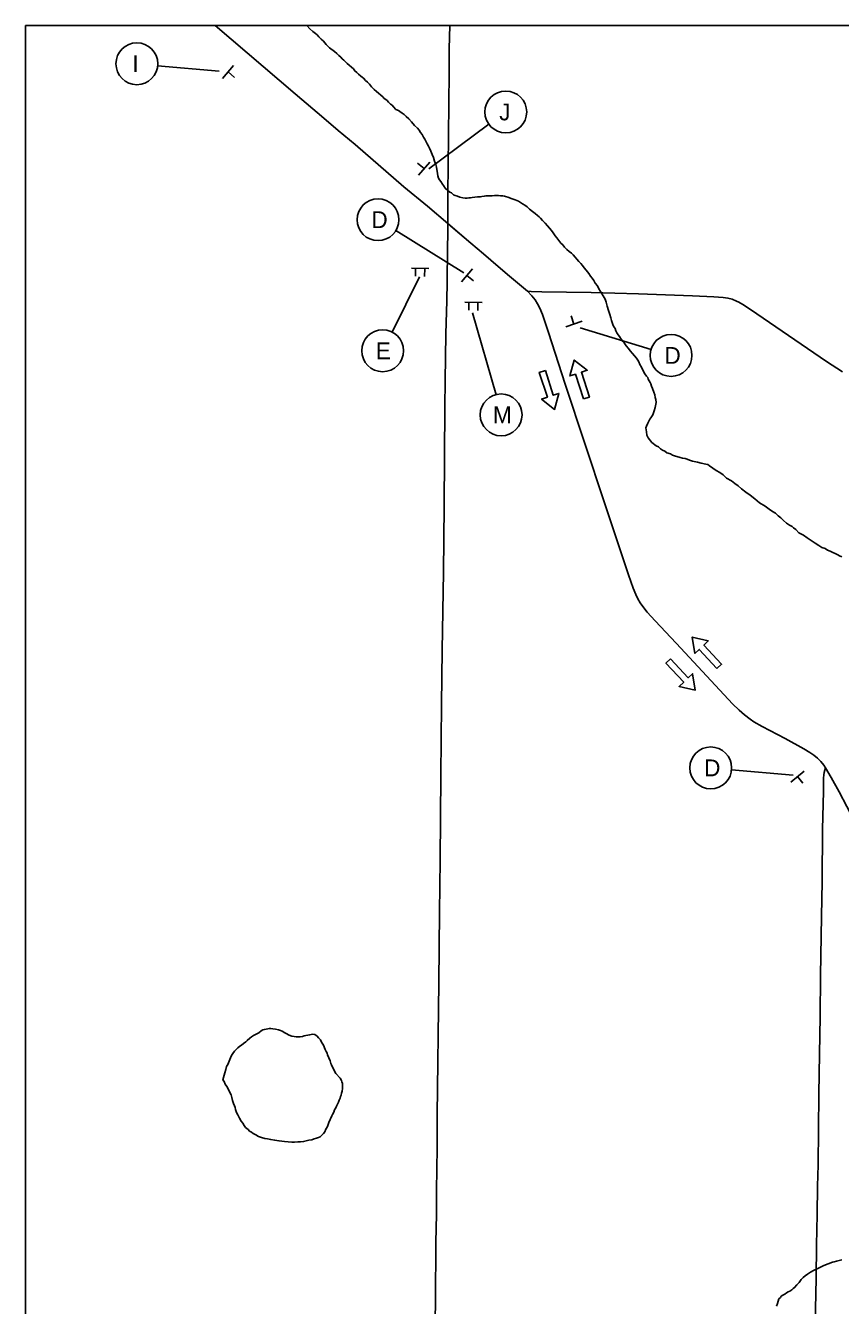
# Model space of a CAD drawing. Extents: x 1633.3 to 1707.6, y 1081.5 to 1106.
# Drawn here: x 1633.31 to 1640.87, y 1094.16 to 1106.02 of the extents above; entities that cross this region are included whole.
import ezdxf

# ---------------------------------------------------------------- set-up
doc = ezdxf.new("R2010")
doc.units = 0
for name, color, linetype in [('GM_X_County_Road', 7, 'Continuous'), ('GM_X_Minor_Lake', 7, 'Continuous'), ('GM_X_Minor_River', 7, 'Continuous'), ('GM_X_State_Route', 7, 'Continuous'), ('GM_X_Township_Road', 7, 'Continuous'), ('SH_Data', 7, 'Continuous'), ('SH_Text', 7, 'Continuous'), ('SN_P_Signs', 7, 'Continuous')]:
    doc.layers.add(name, color=color, linetype=linetype)

msp = doc.modelspace()

# ---------------------------------------------------------------- linework, layer by layer
at = {"layer": 'GM_X_County_Road'}
for points in [[(1637.23, 1104.185), (1637.23, 1104.472), (1637.232, 1104.713), (1637.241, 1105.587), (1637.241, 1105.806), (1637.246, 1106.021)], [(1637.108, 1093.581), (1637.115, 1094.281), (1637.118, 1094.653), (1637.118, 1094.74), (1637.123, 1095.003), (1637.123, 1095.221), (1637.128, 1095.615), (1637.131, 1095.922), (1637.145, 1097.147), (1637.148, 1097.476), (1637.152, 1097.802), (1637.157, 1098.283), (1637.163, 1099.071), (1637.171, 1099.728), (1637.177, 1100.231), (1637.189, 1100.953), (1637.195, 1101.566), (1637.201, 1102.485), (1637.203, 1102.726), (1637.21, 1103.164), (1637.218, 1103.47), (1637.221, 1103.645), (1637.225, 1103.952), (1637.228, 1104.104), (1637.23, 1104.185)]]:
    msp.add_lwpolyline(points, dxfattribs=at)
at = {"layer": 'GM_X_Minor_Lake'}
for points in [[(1636.191, 1096.306), (1636.16, 1096.364), (1636.15, 1096.386), (1636.144, 1096.399), (1636.137, 1096.424), (1636.113, 1096.48), (1636.108, 1096.494), (1636.1, 1096.51), (1636.092, 1096.529), (1636.084, 1096.545), (1636.077, 1096.561), (1636.069, 1096.577), (1636.058, 1096.596), (1636.048, 1096.618), (1636.029, 1096.637), (1636.016, 1096.653), (1635.995, 1096.667), (1635.976, 1096.669), (1635.96, 1096.667), (1635.946, 1096.664), (1635.93, 1096.662), (1635.911, 1096.657), (1635.895, 1096.654), (1635.879, 1096.649), (1635.857, 1096.644), (1635.836, 1096.644), (1635.822, 1096.645), (1635.804, 1096.648), (1635.782, 1096.653), (1635.756, 1096.662), (1635.729, 1096.675), (1635.716, 1096.684), (1635.692, 1096.697), (1635.675, 1096.703), (1635.657, 1096.711), (1635.63, 1096.717), (1635.606, 1096.72), (1635.587, 1096.723), (1635.574, 1096.723), (1635.528, 1096.715), (1635.514, 1096.71), (1635.498, 1096.7), (1635.474, 1096.684), (1635.452, 1096.671), (1635.439, 1096.663), (1635.425, 1096.658), (1635.409, 1096.647), (1635.393, 1096.632), (1635.368, 1096.61), (1635.355, 1096.6), (1635.333, 1096.584), (1635.314, 1096.568), (1635.3, 1096.558), (1635.281, 1096.542), (1635.262, 1096.526), (1635.251, 1096.513), (1635.235, 1096.492), (1635.221, 1096.473), (1635.213, 1096.452), (1635.205, 1096.436), (1635.199, 1096.42), (1635.188, 1096.39), (1635.177, 1096.369), (1635.169, 1096.343), (1635.161, 1096.311)], [(1635.161, 1096.311), (1635.143, 1096.248), (1635.154, 1096.23), (1635.164, 1096.206), (1635.178, 1096.184), (1635.218, 1096.109), (1635.226, 1096.082), (1635.231, 1096.056), (1635.242, 1096.029), (1635.25, 1096.005), (1635.255, 1095.991), (1635.26, 1095.973), (1635.268, 1095.943), (1635.281, 1095.922), (1635.297, 1095.892), (1635.313, 1095.865), (1635.327, 1095.844), (1635.34, 1095.822), (1635.353, 1095.806), (1635.375, 1095.785), (1635.388, 1095.771), (1635.407, 1095.761), (1635.423, 1095.75), (1635.447, 1095.736), (1635.471, 1095.723), (1635.5, 1095.712), (1635.53, 1095.704), (1635.557, 1095.699), (1635.586, 1095.693), (1635.621, 1095.688), (1635.664, 1095.68), (1635.712, 1095.674), (1635.749, 1095.671), (1635.781, 1095.669), (1635.805, 1095.668), (1635.837, 1095.671), (1635.862, 1095.671), (1635.891, 1095.674), (1635.915, 1095.681), (1635.939, 1095.687), (1635.966, 1095.692), (1635.99, 1095.7), (1636.011, 1095.705), (1636.028, 1095.711), (1636.044, 1095.719), (1636.057, 1095.732), (1636.076, 1095.748), (1636.087, 1095.764), (1636.097, 1095.788), (1636.108, 1095.807), (1636.116, 1095.825), (1636.124, 1095.852), (1636.154, 1095.913), (1636.159, 1095.927), (1636.17, 1095.946), (1636.178, 1095.97), (1636.189, 1095.986), (1636.197, 1096.004), (1636.205, 1096.02), (1636.213, 1096.039), (1636.221, 1096.058), (1636.229, 1096.076), (1636.234, 1096.092), (1636.24, 1096.106), (1636.243, 1096.122), (1636.248, 1096.143), (1636.251, 1096.165), (1636.251, 1096.186), (1636.253, 1096.199), (1636.251, 1096.213), (1636.245, 1096.229), (1636.243, 1096.242), (1636.229, 1096.261), (1636.191, 1096.306)]]:
    msp.add_lwpolyline(points, dxfattribs=at)
at = {"layer": 'GM_X_Minor_River'}
for points in [[(1635.92, 1106.021), (1635.948, 1105.992), (1635.977, 1105.967), (1636.001, 1105.948), (1636.017, 1105.934), (1636.033, 1105.915), (1636.054, 1105.896), (1636.076, 1105.875), (1636.099, 1105.845)], [(1636.099, 1105.845), (1636.131, 1105.815), (1636.176, 1105.78), (1636.198, 1105.761), (1636.216, 1105.744), (1636.235, 1105.728), (1636.248, 1105.714), (1636.264, 1105.701), (1636.28, 1105.685), (1636.296, 1105.668), (1636.352, 1105.619), (1636.365, 1105.6), (1636.384, 1105.587), (1636.399, 1105.57), (1636.423, 1105.551), (1636.447, 1105.532), (1636.466, 1105.513), (1636.484, 1105.497), (1636.503, 1105.478), (1636.521, 1105.454), (1636.545, 1105.429), (1636.567, 1105.41), (1636.585, 1105.394), (1636.606, 1105.375), (1636.625, 1105.359), (1636.638, 1105.345), (1636.652, 1105.337), (1636.665, 1105.326), (1636.678, 1105.31), (1636.697, 1105.291), (1636.713, 1105.282), (1636.726, 1105.269), (1636.747, 1105.244), (1636.771, 1105.233), (1636.784, 1105.225), (1636.806, 1105.209), (1636.824, 1105.195), (1636.843, 1105.179), (1636.867, 1105.157), (1636.891, 1105.127), (1636.92, 1105.095), (1636.946, 1105.07), (1636.962, 1105.051), (1636.975, 1105.03), (1636.989, 1105.011), (1637.002, 1104.987), (1637.015, 1104.968), (1637.023, 1104.949), (1637.036, 1104.925), (1637.049, 1104.903), (1637.057, 1104.884), (1637.07, 1104.857), (1637.083, 1104.825), (1637.096, 1104.798), (1637.106, 1104.763), (1637.117, 1104.733), (1637.122, 1104.707), (1637.132, 1104.65), (1637.137, 1104.629), (1637.142, 1104.607), (1637.152, 1104.591), (1637.163, 1104.575), (1637.179, 1104.55), (1637.189, 1104.537), (1637.203, 1104.515), (1637.229, 1104.491), (1637.248, 1104.477), (1637.261, 1104.469), (1637.282, 1104.453), (1637.298, 1104.447), (1637.317, 1104.439), (1637.341, 1104.43), (1637.368, 1104.425), (1637.389, 1104.422), (1637.408, 1104.422), (1637.422, 1104.424), (1637.438, 1104.424), (1637.454, 1104.426), (1637.478, 1104.429), (1637.505, 1104.434), (1637.529, 1104.433), (1637.543, 1104.436), (1637.567, 1104.438), (1637.58, 1104.441), (1637.602, 1104.443), (1637.623, 1104.443), (1637.639, 1104.443), (1637.661, 1104.445), (1637.682, 1104.445), (1637.698, 1104.444), (1637.717, 1104.442), (1637.739, 1104.441), (1637.755, 1104.438), (1637.795, 1104.427), (1637.816, 1104.419), (1637.835, 1104.413), (1637.854, 1104.405), (1637.87, 1104.399), (1637.883, 1104.394), (1637.904, 1104.38), (1637.92, 1104.369)], [(1637.92, 1104.369), (1637.942, 1104.356), (1637.963, 1104.339), (1637.987, 1104.32), (1638.014, 1104.296), (1638.04, 1104.279), (1638.059, 1104.26), (1638.075, 1104.249), (1638.088, 1104.236), (1638.106, 1104.214), (1638.13, 1104.19), (1638.152, 1104.165), (1638.17, 1104.144), (1638.189, 1104.122), (1638.207, 1104.098), (1638.223, 1104.073), (1638.239, 1104.052), (1638.257, 1104.027), (1638.278, 1104.003), (1638.294, 1103.987), (1638.31, 1103.968), (1638.331, 1103.946), (1638.355, 1103.927), (1638.377, 1103.911), (1638.392, 1103.894), (1638.408, 1103.875), (1638.424, 1103.856), (1638.445, 1103.835), (1638.461, 1103.816), (1638.477, 1103.797), (1638.493, 1103.775), (1638.512, 1103.753), (1638.525, 1103.737), (1638.535, 1103.721), (1638.551, 1103.699), (1638.567, 1103.678), (1638.583, 1103.656), (1638.596, 1103.634), (1638.617, 1103.607), (1638.63, 1103.58), (1638.646, 1103.556), (1638.678, 1103.499), (1638.688, 1103.483), (1638.696, 1103.456), (1638.706, 1103.421), (1638.719, 1103.378), (1638.732, 1103.341), (1638.74, 1103.311), (1638.747, 1103.287), (1638.755, 1103.26), (1638.763, 1103.241), (1638.771, 1103.225), (1638.779, 1103.212), (1638.786, 1103.19), (1638.797, 1103.171), (1638.807, 1103.155), (1638.821, 1103.139), (1638.831, 1103.122), (1638.839, 1103.109), (1638.852, 1103.093), (1638.863, 1103.079), (1638.884, 1103.052), (1638.903, 1103.028), (1638.921, 1103.006), (1638.942, 1102.982), (1638.961, 1102.96), (1638.977, 1102.938), (1638.99, 1102.919), (1639, 1102.903), (1639.008, 1102.879), (1639.024, 1102.855), (1639.037, 1102.825), (1639.055, 1102.793), (1639.071, 1102.771), (1639.082, 1102.758), (1639.087, 1102.744), (1639.095, 1102.728), (1639.105, 1102.712), (1639.111, 1102.698), (1639.118, 1102.679), (1639.126, 1102.655), (1639.139, 1102.623), (1639.147, 1102.596), (1639.152, 1102.572), (1639.157, 1102.553), (1639.162, 1102.526), (1639.153, 1102.481), (1639.142, 1102.449), (1639.131, 1102.411), (1639.112, 1102.385), (1639.101, 1102.372), (1639.085, 1102.334), (1639.071, 1102.308), (1639.065, 1102.292), (1639.07, 1102.254), (1639.075, 1102.225), (1639.088, 1102.198), (1639.12, 1102.157), (1639.16, 1102.124), (1639.181, 1102.116), (1639.202, 1102.097)], [(1639.202, 1102.097), (1639.218, 1102.086), (1639.24, 1102.075), (1639.261, 1102.059), (1639.293, 1102.05), (1639.312, 1102.039), (1639.33, 1102.031), (1639.384, 1102.017), (1639.405, 1102.011), (1639.429, 1102.006), (1639.448, 1102), (1639.47, 1101.992), (1639.499, 1101.983), (1639.545, 1101.972), (1639.579, 1101.963), (1639.62, 1101.955), (1639.641, 1101.952), (1639.657, 1101.938), (1639.686, 1101.919), (1639.718, 1101.897), (1639.75, 1101.878), (1639.782, 1101.856), (1639.814, 1101.826), (1639.859, 1101.799), (1639.891, 1101.777), (1639.92, 1101.753), (1639.952, 1101.726), (1639.992, 1101.696), (1640.032, 1101.666), (1640.075, 1101.633), (1640.12, 1101.597), (1640.171, 1101.565), (1640.21, 1101.537), (1640.24, 1101.516), (1640.269, 1101.499), (1640.293, 1101.475), (1640.317, 1101.456), (1640.341, 1101.431), (1640.37, 1101.409), (1640.399, 1101.39), (1640.421, 1101.377), (1640.434, 1101.366), (1640.455, 1101.349), (1640.484, 1101.319), (1640.527, 1101.297), (1640.562, 1101.273), (1640.599, 1101.246), (1640.636, 1101.221), (1640.671, 1101.202), (1640.697, 1101.183), (1640.727, 1101.172), (1640.751, 1101.158), (1640.775, 1101.147), (1640.847, 1101.114), (1640.86, 1101.106), (1640.884, 1101.095)], [(1640.884, 1094.579), (1640.857, 1094.571), (1640.833, 1094.566), (1640.812, 1094.561), (1640.796, 1094.556), (1640.715, 1094.526), (1640.686, 1094.51), (1640.654, 1094.495), (1640.619, 1094.479), (1640.592, 1094.463), (1640.565, 1094.444), (1640.544, 1094.431), (1640.525, 1094.415), (1640.506, 1094.396), (1640.488, 1094.369), (1640.466, 1094.345), (1640.445, 1094.321), (1640.431, 1094.311), (1640.418, 1094.3), (1640.402, 1094.289), (1640.386, 1094.281), (1640.37, 1094.273), (1640.354, 1094.26), (1640.335, 1094.252), (1640.321, 1094.241), (1640.313, 1094.228), (1640.3, 1094.215), (1640.292, 1094.196), (1640.286, 1094.172), (1640.278, 1094.148)]]:
    msp.add_lwpolyline(points, dxfattribs=at)
at = {"layer": 'GM_X_State_Route'}
for points in [[(1635.071, 1106.021), (1635.813, 1105.388), (1636.078, 1105.161), (1636.211, 1105.047), (1636.37, 1104.918), (1636.821, 1104.525), (1637.039, 1104.347), (1637.23, 1104.185), (1637.278, 1104.144)], [(1637.278, 1104.144), (1637.441, 1104.005), (1637.558, 1103.906), (1637.627, 1103.845), (1637.783, 1103.713), (1637.93, 1103.591), (1637.966, 1103.559), (1638.009, 1103.514), (1638.037, 1103.479), (1638.061, 1103.442), (1638.081, 1103.402), (1638.105, 1103.341), (1638.161, 1103.174), (1638.318, 1102.696), (1638.683, 1101.595), (1638.903, 1100.93), (1638.947, 1100.806), (1638.972, 1100.746), (1638.992, 1100.707), (1639.013, 1100.67), (1639.038, 1100.634), (1639.078, 1100.583), (1639.151, 1100.501), (1639.345, 1100.294), (1639.63, 1099.99), (1639.869, 1099.734), (1639.931, 1099.673), (1639.98, 1099.63), (1640.032, 1099.591), (1640.068, 1099.567), (1640.144, 1099.524), (1640.356, 1099.41), (1640.53, 1099.317), (1640.586, 1099.283), (1640.623, 1099.257), (1640.657, 1099.229), (1640.688, 1099.197), (1640.715, 1099.163), (1640.731, 1099.14), (1640.785, 1099.05), (1640.858, 1098.916), (1641.073, 1098.509)]]:
    msp.add_lwpolyline(points, dxfattribs=at)
at = {"layer": 'GM_X_Township_Road'}
for points in [[(1637.966, 1103.559), (1638, 1103.557), (1638.1, 1103.553), (1638.559, 1103.546), (1638.997, 1103.534), (1639.499, 1103.515), (1639.696, 1103.507), (1639.783, 1103.5), (1639.826, 1103.494), (1639.867, 1103.483), (1639.907, 1103.467), (1639.926, 1103.458), (1639.964, 1103.436), (1640.037, 1103.389), (1640.506, 1103.066), (1640.741, 1102.906), (1640.888, 1102.811)], [(1640.627, 1092.939), (1640.638, 1094.122), (1640.644, 1094.407), (1640.649, 1094.714), (1640.653, 1094.999), (1640.658, 1095.262), (1640.662, 1095.458), (1640.67, 1096.115), (1640.676, 1096.489), (1640.682, 1096.832), (1640.686, 1097.214), (1640.694, 1097.761), (1640.699, 1098.086), (1640.705, 1098.572), (1640.712, 1098.92), (1640.712, 1099.044), (1640.716, 1099.076), (1640.718, 1099.096), (1640.731, 1099.14)]]:
    msp.add_lwpolyline(points, dxfattribs=at)
at = {"layer": 'SH_Data'}
msp.add_lwpolyline([(1633.312, 1106.021), (1648.012, 1106.021), (1648.012, 1086.421), (1633.312, 1086.421)], close=True, dxfattribs=at)
at = {"layer": 'SH_Text'}
for p, q in [((1635.107, 1105.599), (1634.537, 1105.648)), ((1637.052, 1104.692), (1637.609, 1105.107)), ((1637.377, 1103.73), (1636.745, 1104.12)), ((1636.965, 1103.692), (1636.712, 1103.178)), ((1637.458, 1103.357), (1637.676, 1102.599)), ((1638.457, 1103.218), (1639.113, 1103.019)), ((1638.401, 1102.92), (1638.36, 1102.773)), ((1638.401, 1102.92), (1638.521, 1102.825)), ((1638.077, 1102.806), (1638.133, 1102.824)), ((1638.152, 1102.576), (1638.077, 1102.806)), ((1638.207, 1102.594), (1638.133, 1102.824)), ((1638.36, 1102.773), (1638.412, 1102.789)), ((1638.412, 1102.789), (1638.486, 1102.559)), ((1638.521, 1102.825), (1638.467, 1102.807)), ((1638.467, 1102.807), (1638.542, 1102.577)), ((1638.098, 1102.558), (1638.152, 1102.576)), ((1638.218, 1102.463), (1638.098, 1102.558)), ((1638.259, 1102.61), (1638.207, 1102.594)), ((1638.218, 1102.463), (1638.259, 1102.61)), ((1638.542, 1102.577), (1638.486, 1102.559)), ((1639.495, 1100.351), (1639.644, 1100.316)), ((1639.495, 1100.351), (1639.52, 1100.2)), ((1639.644, 1100.316), (1639.603, 1100.277)), ((1639.603, 1100.277), (1639.768, 1100.1)), ((1639.251, 1100.111), (1639.293, 1100.151)), ((1639.458, 1099.974), (1639.293, 1100.151)), ((1639.52, 1100.2), (1639.56, 1100.237)), ((1639.56, 1100.237), (1639.725, 1100.061)), ((1639.416, 1099.934), (1639.251, 1100.111)), ((1639.768, 1100.1), (1639.725, 1100.061)), ((1639.374, 1099.895), (1639.416, 1099.934)), ((1639.523, 1099.86), (1639.374, 1099.895)), ((1639.498, 1100.011), (1639.458, 1099.974)), ((1639.523, 1099.86), (1639.498, 1100.011)), ((1640.43, 1099.071), (1639.86, 1099.12))]:
    msp.add_line(p, q, dxfattribs=at)
msp.add_lwpolyline([(1637.23, 1104.185), (1637.441, 1104.005), (1637.558, 1103.906), (1637.627, 1103.845), (1637.783, 1103.713), (1637.93, 1103.591), (1637.966, 1103.559), (1638.009, 1103.514), (1638.037, 1103.479), (1638.061, 1103.442), (1638.081, 1103.402), (1638.105, 1103.341), (1638.161, 1103.174), (1638.318, 1102.696), (1638.683, 1101.595), (1638.903, 1100.93), (1638.947, 1100.806), (1638.972, 1100.746), (1638.992, 1100.707), (1639.013, 1100.67), (1639.038, 1100.634), (1639.078, 1100.583), (1639.151, 1100.501), (1639.345, 1100.294), (1639.63, 1099.99), (1639.869, 1099.734), (1639.931, 1099.673), (1639.98, 1099.63), (1640.032, 1099.591), (1640.068, 1099.567), (1640.144, 1099.524), (1640.356, 1099.41), (1640.53, 1099.317), (1640.586, 1099.283), (1640.623, 1099.257), (1640.657, 1099.229), (1640.688, 1099.197), (1640.715, 1099.163), (1640.731, 1099.14), (1640.785, 1099.05), (1640.858, 1098.916), (1641.073, 1098.509)], dxfattribs=at)
for points in [[(1638.486, 1102.559), (1638.412, 1102.789), (1638.36, 1102.773), (1638.401, 1102.92), (1638.521, 1102.825), (1638.467, 1102.807), (1638.542, 1102.577)], [(1638.133, 1102.824), (1638.207, 1102.594), (1638.259, 1102.61), (1638.218, 1102.463), (1638.098, 1102.558), (1638.152, 1102.576), (1638.077, 1102.806)], [(1639.725, 1100.061), (1639.56, 1100.237), (1639.52, 1100.2), (1639.495, 1100.351), (1639.644, 1100.316), (1639.603, 1100.277), (1639.768, 1100.1)], [(1639.293, 1100.151), (1639.458, 1099.974), (1639.498, 1100.011), (1639.523, 1099.86), (1639.374, 1099.895), (1639.416, 1099.934), (1639.251, 1100.111)]]:
    msp.add_lwpolyline(points, close=True, dxfattribs=at)
for centre in [(1634.344, 1105.667), (1637.766, 1105.22), (1636.581, 1104.221), (1636.624, 1103.006), (1639.299, 1102.963), (1637.723, 1102.412), (1639.667, 1099.139)]:
    msp.add_circle(centre, 0.194, dxfattribs=at)
at = {"layer": 'SN_P_Signs'}
for p, q in [((1635.242, 1105.651), (1635.138, 1105.53)), ((1635.19, 1105.591), (1635.251, 1105.539)), ((1637.008, 1104.695), (1636.947, 1104.746)), ((1636.956, 1104.634), (1637.06, 1104.756)), ((1636.893, 1103.773), (1637.053, 1103.768)), ((1636.93, 1103.772), (1636.928, 1103.697)), ((1637.014, 1103.769), (1637.012, 1103.694)), ((1637.458, 1103.766), (1637.354, 1103.644)), ((1637.406, 1103.705), (1637.467, 1103.653)), ((1637.387, 1103.458), (1637.547, 1103.453)), ((1637.424, 1103.457), (1637.422, 1103.382)), ((1637.508, 1103.454), (1637.506, 1103.379)), ((1638.323, 1103.228), (1638.474, 1103.279)), ((1638.398, 1103.253), (1638.373, 1103.329)), ((1640.532, 1099.11), (1640.41, 1099.007)), ((1640.471, 1099.058), (1640.522, 1098.997))]:
    msp.add_line(p, q, dxfattribs=at)

# ---------------------------------------------------------------- texts
at = {"layer": 'SH_Text'}
for s, p in [('I', (1634.303, 1105.589)), ('J', (1637.705, 1105.142)), ('D', (1636.52, 1104.143)), ('E', (1636.561, 1102.928)), ('D', (1639.238, 1102.885)), ('M', (1637.647, 1102.334)), ('D', (1639.606, 1099.061))]:
    msp.add_text(s, height=0.156, dxfattribs=at).set_placement(p)

doc.saveas('drawing.dxf')
